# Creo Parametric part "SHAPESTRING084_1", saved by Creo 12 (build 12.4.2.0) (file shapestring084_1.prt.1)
Units: Custom; MM, KILOGRAM, SECS

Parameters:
  PTC_WM_ITERATION = "0"
  PTC_WM_VERSION = "-.0"
  PTC_WM_LIFECYCLE_STATE = "In Work"
  PTC_WM_LIFECYCLE = "MO_CADDocument"
  PTC_WM_CREATED_BY = "Maximilian Roepper (Z0017RMS: MO)"
  PTC_WM_CREATED_ON = "18-Sep-26 11:36:42 AM"
  PTC_WM_MODIFIED_BY = "Maximilian Roepper (Z0017RMS: MO)"
  PTC_WM_MODIFIED_ON = "18-Sep-26 11:36:46 AM"
  PDMLINKNUMBER = "PDM000071455259"
  PTC_WM_NAME = "shapestring084_1.prt"
  PTC_WM_NUMBER = "PDM000071455259"

Other parameters: WEIGHT, WEIGHT_FACTOR, WEIGHT_ADD, _MASS_TEMP, _DIFF_TEMP, MC_ERRORS, SUPPLIER

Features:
  1. coordinate system
  2. datum plane "PRT_YZ"
  3. datum plane "PRT_XY"
  4. datum plane "PRT_XZ"
  5. coordinate system
  6. datum axis
  7. datum axis
  8. datum axis
  9. coordinate system
  10. imported feature
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
Other named items: PRT, SIEMENS_MO, DRW_VIEW_ORG, PRT_X, PRT_Y, PRT_Z, CS0, ROUGH_GROB

Layers: 00_STD_CSYS-KSYS, 01_STD_PLANES-EBENEN, 02_STD_AXES-ACHSEN, 03_STD_CSYS-KSYS, 24_IMPORT_FEAT-IMPORT_KE, INTFCLR

Surfaces: 1 plane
